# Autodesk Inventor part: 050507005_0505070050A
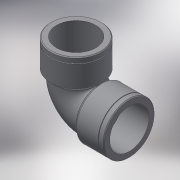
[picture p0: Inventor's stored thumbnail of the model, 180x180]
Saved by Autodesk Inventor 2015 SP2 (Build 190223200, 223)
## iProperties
Created: 2017-05
Part Number: 050507005_0505070050A
Material: Generic
Description: PLASSON THREADED ELBOW 1/2"-1/2"
Document SubType Name: Modeling
Designer: KIM
Density: 1 g/cm^3
Appearance: Default
Author: KIM
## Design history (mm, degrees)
derived "050507.ipt"
feature "Solid1::050507.ipt"
tag "TaggingFeature1"
workaxis "Work Axis4"
body "Solid1"
other parameters: "d0" = 32, "d2" = 0.5, "d3" = 0.5, "d4" = 24.2203, "d5" = 18.631, "d6" = 17, "d7" = 135 deg, "d8" = 19.55, "d9" = 3.25833, "d19" = 0.37262, "d27" = 17, "d30" = 16.7679, "d31" = 20.4941, "d33" = 90 deg, "d35" = 90 deg, "d36" = 90 deg, "d37" = 0.93155, "Rp_" = 18.631, "A_" = 32, "l_2" = 17
